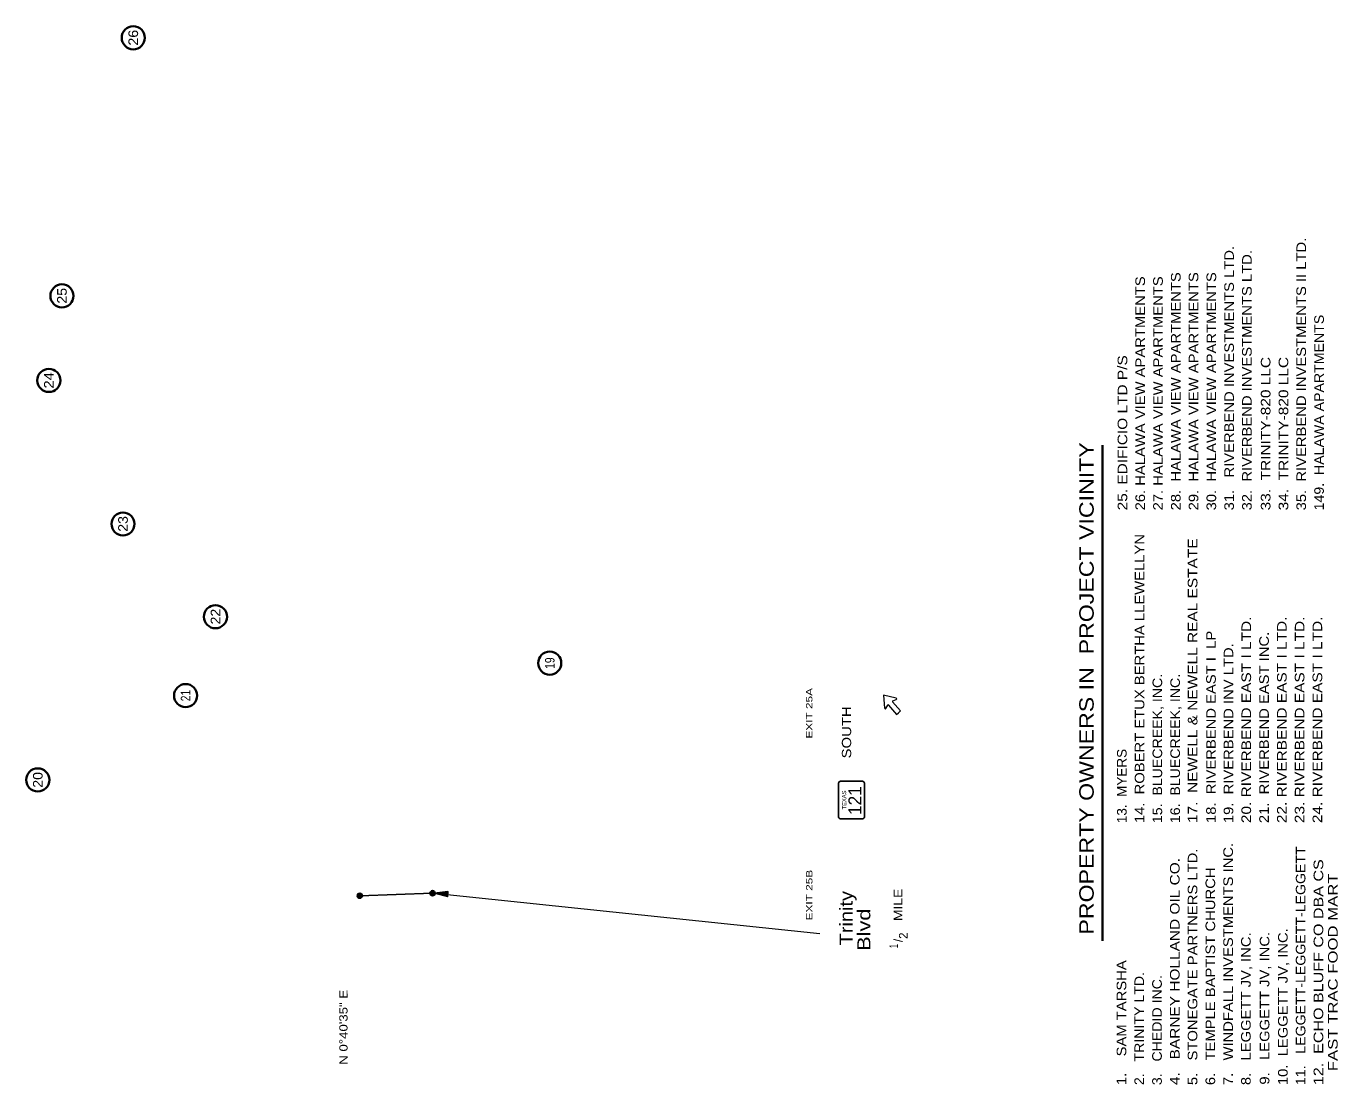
# Model space of a CAD drawing. Extents: x 2363427 to 2368559, y 6957299 to 6980140.
# Drawn here: x 2363942 to 2365853, y 6972350 to 6973892 of the extents above; entities that cross this region are included whole.
import ezdxf
from ezdxf.enums import TextEntityAlignment as Align

# ---------------------------------------------------------------- set-up
doc = ezdxf.new("R2010")
doc.units = 0
doc.header["$LTSCALE"] = 5.6
for name, color, linetype, lineweight in [('17', 7, 'Continuous', 35), ('18', 7, 'Continuous', 35), ('48', 7, 'Continuous', 25)]:
    doc.layers.add(name, color=color, linetype=linetype, lineweight=lineweight)
doc.layers.add('28', color=7, linetype='Continuous')

msp = doc.modelspace()

# ---------------------------------------------------------------- hatches: boundary and pattern name
at = {"layer": '48'}
for points in [[(2364532.345, 6972625.627, 1), (2364535.489, 6972632.396, 1)], [(2364426.369, 6972621.926, 1), (2364429.513, 6972628.695, 1)], [(2364536.999, 6972629.205), (2364555.851, 6972624.082), (2364556.427, 6972631.258)]]:
    msp.add_hatch(color=256, dxfattribs=at).paths.add_polyline_path(points)

# ---------------------------------------------------------------- linework, layer by layer
at = {"layer": '17'}
for centre in [(2364097.934, 6973875.006), (2363994.046, 6973499.106), (2363975.002, 6973375.91), (2364082.981, 6973166.813), (2364217.712, 6973031.774), (2364704.684, 6972964.102), (2364174.24, 6972916.855), (2363958.86, 6972794.052)]:
    msp.add_circle(centre, 16.828, dxfattribs=at)
at = {"layer": '18'}
msp.add_line((2365509.894, 6972559.599), (2365509.894, 6973281.738), dxfattribs=at)
at = {"layer": '48', "lineweight": 13}
for p, q in [((2365194.453, 6972898.119), (2365197.155, 6972902.912)), ((2365198.258, 6972903.069), (2365198.268, 6972903.084)), ((2365204.272, 6972909.067), (2365209.459, 6972911.018)), ((2364536.999, 6972629.205), (2365098.101, 6972570.354))]:
    msp.add_line(p, q, dxfattribs=at)
at = {"layer": '48'}
for p, q in [((2365125.395, 6972789.355), (2365125.388, 6972740.108)), ((2365160.145, 6972792.152), (2365128.2, 6972792.159)), ((2365162.949, 6972740.107), (2365162.957, 6972789.347)), ((2365128.201, 6972737.302), (2365160.144, 6972737.294)), ((2364533.915, 6972629.017), (2364427.936, 6972625.315))]:
    msp.add_line(p, q, dxfattribs=at)
at = {"layer": '48', "lineweight": 13}
for points in [[(2365209.266, 6972912.944), (2365190.656, 6972917.6), (2365192.564, 6972898.548)], [(2365198.268, 6972903.084), (2365209.927, 6972889.478), (2365212.785, 6972891.95), (2365215.713, 6972894.482), (2365203.961, 6972907.951)]]:
    msp.add_lwpolyline(points, dxfattribs=at)
at = {"layer": '48'}
msp.add_lwpolyline([(2364536.999, 6972629.205), (2364555.851, 6972624.082), (2364556.427, 6972631.258)], close=True, dxfattribs=at)
for centre in [(2364533.917, 6972629.012), (2364427.941, 6972625.31)]:
    msp.add_circle(centre, 3.732, dxfattribs=at)
at = {"layer": '48', "lineweight": 13}
for centre, radius, start, end in [((2365197.747, 6972902.629), 0.675, 40.71842, 150.70152), ((2365204.497, 6972908.44), 0.675, 110.73531, 220.71842), ((2365209.07, 6972911.967), 1.012, 290.59878, 75.97992), ((2365193.578, 6972898.633), 1.012, 185.45691, 330.83805)]:
    msp.add_arc(centre, radius, start, end, dxfattribs=at)
at = {"layer": '48'}
for centre, start, end in [((2365128.207, 6972789.348), 89.9985, 179.9985), ((2365160.14, 6972789.347), 359.9985, 89.9985), ((2365128.206, 6972740.108), 179.9985, 269.9985), ((2365160.138, 6972740.108), 269.9985, 359.9985)]:
    msp.add_arc(centre, 2.813, start, end, dxfattribs=at)

# ---------------------------------------------------------------- texts
at = {"layer": '17'}
for s, width, p in [('26', 1.1, (2364104.934, 6973875.117)), ('25', 1.1, (2364001.046, 6973499.217)), ('24', 1.15, (2363982.002, 6973376.02)), ('23', 1.1, (2364089.981, 6973166.923)), ('22', 1.1, (2364224.712, 6973031.884)), ('19', 0.8, (2364711.684, 6972964.157)), ('21', 0.8, (2364181.241, 6972916.911)), ('20', 1.1, (2363965.86, 6972794.107))]:
    msp.add_text(s, height=14, rotation=90, dxfattribs=dict(at, width=width)).set_placement(p, align=Align.CENTER)
at = {"layer": '18'}
for s, height, width, p in [('31.   RIVERBEND INVESTMENTS LTD.', 14, 1.15, (2365701.342, 6973186.631)), ('35.  RIVERBEND INVESTMENTS II LTD.', 14, 1.15, (2365806.387, 6973186.631)), ('32.  RIVERBEND INVESTMENTS LTD.', 14, 1.15, (2365727.243, 6973186.631)), ('28.  HALAWA VIEW APARTMENTS', 14, 1.15, (2365623.638, 6973186.631)), ('29.  HALAWA VIEW APARTMENTS', 14, 1.15, (2365649.539, 6973186.631)), ('30.  HALAWA VIEW APARTMENTS', 14, 1.15, (2365675.44, 6973186.631)), ('26. HALAWA VIEW APARTMENTS', 14, 1.15, (2365571.835, 6973186.631)), ('27. HALAWA VIEW APARTMENTS', 14, 1.15, (2365597.736, 6973186.631)), ('149.  HALAWA APARTMENTS', 14, 1.1, (2365832.371, 6973186.631)), ('25. EDIFICIO LTD P/S', 14, 1.2, (2365545.934, 6973186.631)), ('33.  TRINITY-820 LLC', 14, 1.2, (2365754.585, 6973186.631)), ('34.  TRINITY-820 LLC', 14, 1.2, (2365780.486, 6973186.631)), ('PROPERTY OWNERS IN  PROJECT VICINITY', 21, 1.2, (2365497.085, 6972568.763)), ('14.  ROBERT ETUX BERTHA LLEWELLYN', 14, 1.15, (2365570.913, 6972731.071)), ('17.  NEWELL & NEWELL REAL ESTATE', 14, 1.2, (2365648.158, 6972731.256)), ('20. RIVERBEND EAST I LTD. ', 14, 1.2, (2365726.32, 6972731.071)), ('22. RIVERBEND EAST I LTD. ', 14, 1.2, (2365778.123, 6972731.071)), ('23. RIVERBEND EAST I LTD. ', 14, 1.2, (2365804.025, 6972731.071)), ('24. RIVERBEND EAST I LTD. ', 14, 1.2, (2365829.926, 6972731.071)), ('18.  RIVERBEND EAST I  LP', 14, 1.15, (2365674.95, 6972731.255)), ('21.  RIVERBEND EAST INC.', 14, 1.15, (2365752.221, 6972731.071)), ('19.  RIVERBEND INV LTD.', 14, 1.15, (2365700.419, 6972731.071)), ('15.  BLUECREEK, INC.', 14, 1.1, (2365596.815, 6972731.071)), ('16.  BLUECREEK, INC.', 14, 1.1, (2365622.716, 6972731.071)), ('13.  MYERS', 14, 1.05, (2365545.012, 6972731.071)), ('5.   STONEGATE PARTNERS LTD.', 14, 1.15, (2365648.1, 6972349.475)), ('7.   WINDFALL INVESTMENTS INC.', 14, 1.15, (2365699.903, 6972349.475)), ('11.   LEGGETT-LEGGETT-LEGGETT', 14, 1.1, (2365805.531, 6972349.475)), ('4.   BARNEY HOLLAND OIL CO.', 14, 1.2, (2365622.199, 6972349.475)), ('12.  ECHO BLUFF CO DBA CS ', 14, 1.25, (2365831.432, 6972349.475)), ('6.   TEMPLE BAPTIST CHURCH', 14, 1.15, (2365674.001, 6972349.475)), ('   FAST TRAC FOOD MART', 14, 1.3, (2365852.432, 6972349.475)), ('10.  LEGGETT JV, INC.', 14, 1.15, (2365779.63, 6972349.475)), ('8.   LEGGETT JV, INC.', 14, 1.15, (2365725.804, 6972349.475)), ('9.   LEGGETT JV, INC.', 14, 1.15, (2365753.029, 6972350.187)), ('1.    SAM TARSHA', 14, 1.15, (2365544.496, 6972349.475)), ('2.   TRINITY LTD.', 14, 1.1, (2365570.397, 6972349.475)), ('3.   CHEDID INC.', 14, 1.1, (2365596.298, 6972349.475))]:
    msp.add_text(s, height=height, rotation=90, dxfattribs=dict(at, width=width)).set_placement(p)
at = {"layer": '28', "width": 1.2}
msp.add_text('N 0°40\'35" E', height=12, rotation=90.109, dxfattribs=at).set_placement((2364410.138, 6972433.724), align=Align.CENTER)
at = {"layer": '48'}
for s, height, rotation, width, p in [('EXIT 25A', 9.188, 90, 1.4, (2365087.319, 6972891.079)), ('SOUTH', 13.5, 89.999, 1.2, (2365143.742, 6972863.313)), ('EXIT 25B', 9.188, 90, 1.4, (2365087.349, 6972626.242)), ('MILE', 12.54, 90, 1.2, (2365218.429, 6972612.03)), ('Trinity', 18.91, 90, 1.15, (2365145.953, 6972592.632)), ('Blvd', 18.9, 90, 1.25, (2365171.702, 6972575.883)), ('1', 12.54, 90, 0.65, (2365212.054, 6972551.986))]:
    msp.add_text(s, height=height, rotation=rotation, dxfattribs=dict(at, width=width)).set_placement(p, align=Align.CENTER)
at = {"layer": '48', "width": 1.05}
msp.add_text('TEXAS', height=6, rotation=89.999, dxfattribs=at).set_placement((2365136.496, 6972750.945))
at = {"layer": '48'}
msp.add_text('121', height=18.75, rotation=89.999, dxfattribs=at).set_placement((2365158.546, 6972742.972))
for s, p in [('/', (2365218.429, 6972560.23)), ('2', (2365225.982, 6972567.086))]:
    msp.add_text(s, height=12.54, rotation=90, dxfattribs=at).set_placement(p, align=Align.CENTER)

doc.saveas('drawing.dxf')
